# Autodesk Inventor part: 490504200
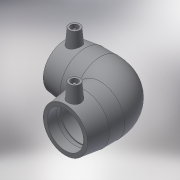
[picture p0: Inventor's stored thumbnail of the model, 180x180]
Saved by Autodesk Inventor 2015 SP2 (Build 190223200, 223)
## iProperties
Created: 2017-06
Part Number: 490504200
Material: Generic
Description: PLASSON 90° ELBOW 200
Document SubType Name: Modeling
Designer: KIM
Mass: 55.0731 g
Surface Area: 148.067 cm^2
Volume: 55.0731 cm^3
Density: 1 g/cm^3
Appearance: Default
Author: KIM
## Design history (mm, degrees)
derived "490504.ipt"
feature "Solid1::490504.ipt"
tag "TaggingFeature1"
body "Solid1"
other parameters: "d2" = 262, "d4" = 112.25, "d5" = 235.8, "d8" = 168 deg, "d10" = 44.8, "d11" = 14.93333, "d14" = 17.6296, "d19" = 3.52592, "d20" = 168 deg, "d22" = 241.04, "d23" = 262, "d24" = 233.8088, "d29" = 124, "d30" = 15, "d31" = 157.15, "d34" = 5 deg, "d35" = 15, "d39" = 5 deg, "d41" = 4, "d42" = 14, "d43" = 0, "d45" = 4, "d46" = 14, "d47" = 0, "d51" = 44.8, "d52" = 112, "d54" = 90 deg, "d67" = 45 deg, "d71" = 90 deg, "d75" = 13.1, "d82" = 45 deg, "d83" = 112, "d84" = 235.8, "d86" = 117.9, "d87" = 90 deg, "d90" = 112, "d91" = 0, "d92" = 112, "d93" = 0, "d94" = 90 deg, "d95" = 120.52, "d98" = 449, "d101" = 3, "d102" = 0, "d103" = 3, "d104" = 0, "d105" = 32.48, "d106" = 8.12, "d107" = 449, "d110" = 61.6, "L_" = 449, "L_1" = 112, "D_" = 262, "A_" = 124, "d_2" = 12
